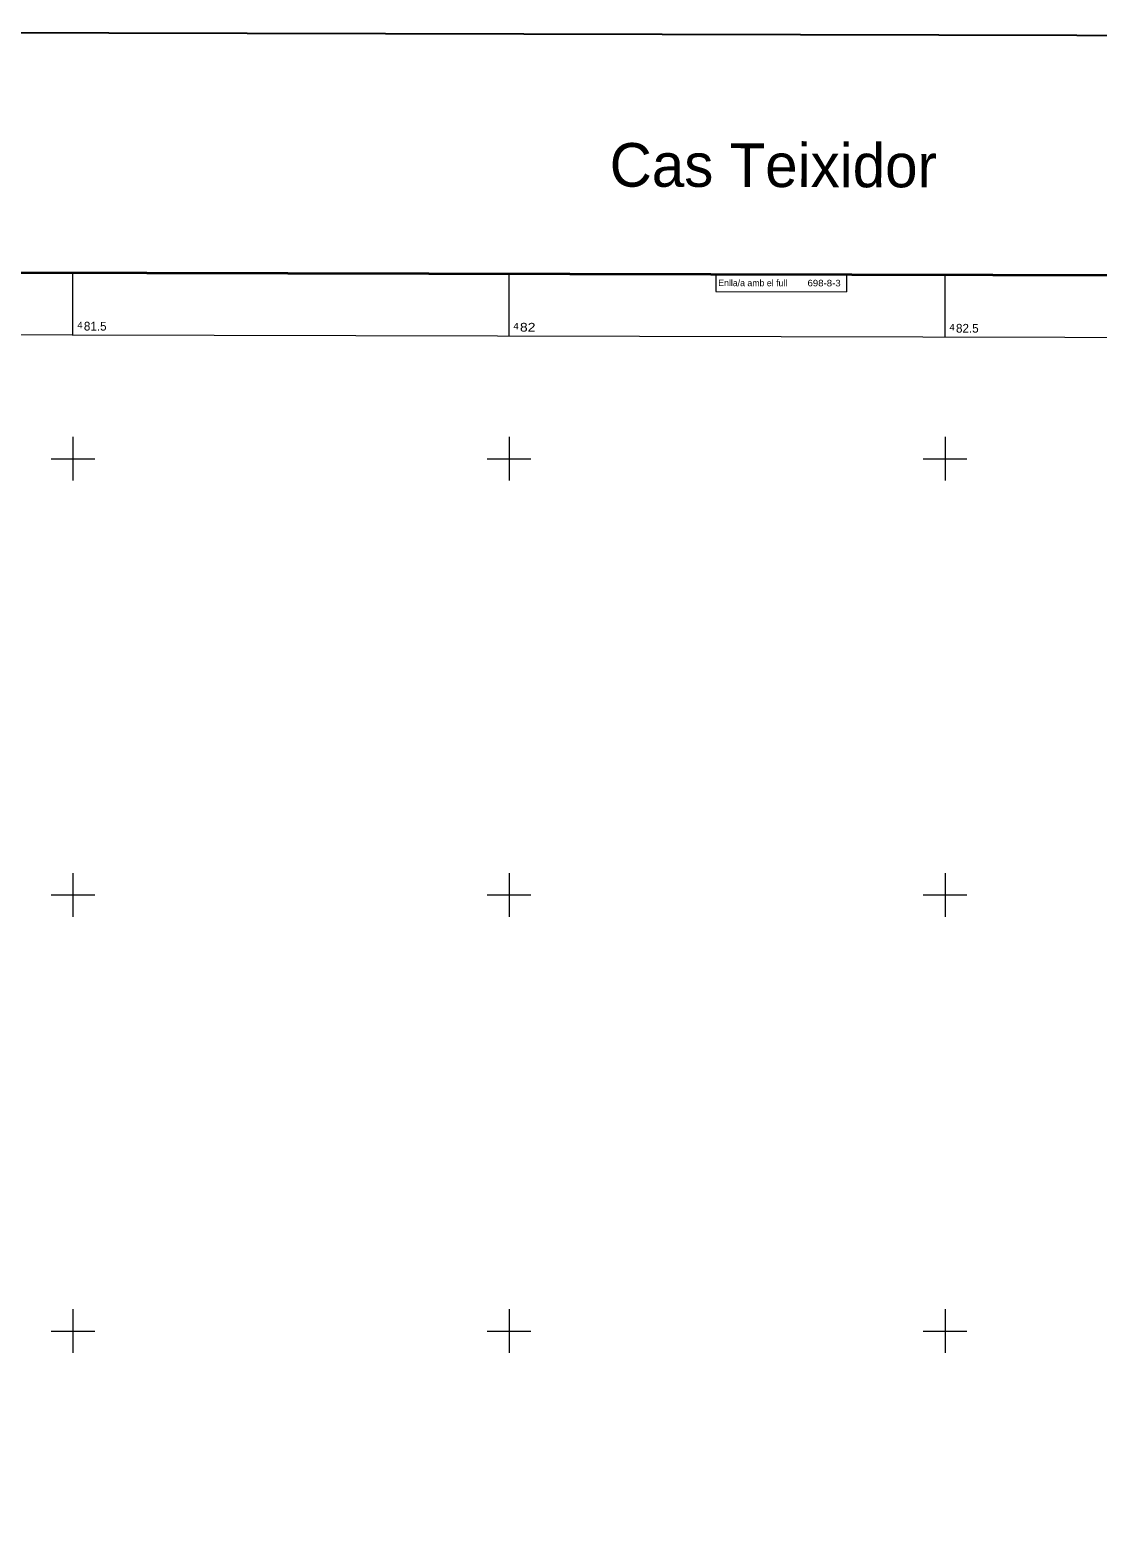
# Model space of a CAD drawing. Extents: x 480264 to 484872, y 4381275 to 4384491.
# Drawn here: x 481451 to 482675, y 4382763 to 4384491 of the extents above; entities that cross this region are included whole.
import ezdxf
from ezdxf.enums import TextEntityAlignment as Align

# ---------------------------------------------------------------- set-up
doc = ezdxf.new("R2010")
doc.units = 0
doc.header["$LTSCALE"] = 4
doc.linetypes.add('DOTTED', pattern=[1.5, 0.3, -1.2])
doc.layers.add('1', color=7, linetype='Continuous', lineweight=13)
doc.layers.add('2', color=7, linetype='DOTTED', lineweight=13)

msp = doc.modelspace()

# ---------------------------------------------------------------- linework, layer by layer
at = {"layer": '1'}
for p, q in [((481500, 4384142.05), (481500, 4384213.42)), ((482000, 4384140.85), (482000, 4384212.24)), ((482387.01, 4384211.32), (482386.97, 4384191.32)), ((482500, 4384139.65), (482500, 4384211.05)), ((481500, 4384025), (481500, 4383975)), ((482000, 4384025), (482000, 4383975)), ((482500, 4384025), (482500, 4383975)), ((481475, 4384000), (481525, 4384000)), ((481975, 4384000), (482025, 4384000)), ((482475, 4384000), (482525, 4384000)), ((481500, 4383525), (481500, 4383475)), ((482000, 4383525), (482000, 4383475)), ((482500, 4383525), (482500, 4383475)), ((481475, 4383500), (481525, 4383500)), ((481975, 4383500), (482025, 4383500)), ((482475, 4383500), (482525, 4383500)), ((481500, 4383025), (481500, 4382975)), ((482000, 4383025), (482000, 4382975)), ((482500, 4383025), (482500, 4382975)), ((481475, 4383000), (481525, 4383000)), ((481975, 4383000), (482025, 4383000)), ((482475, 4383000), (482525, 4383000))]:
    msp.add_line(p, q, dxfattribs=at)
at = {"layer": '1', "lineweight": 25}
msp.add_lwpolyline([(480271.92, 4384491.35), (484871.91, 4384480.42), (484864.3, 4381275.43), (480264.31, 4381286.36)], close=True, dxfattribs=at)
at = {"layer": '1', "lineweight": 35}
msp.add_lwpolyline([(480452.76, 4384215.91), (484171.26, 4384207.08), (484165.43, 4381752.09), (480446.93, 4381760.92)], close=True, dxfattribs=at)
at = {"layer": '1'}
msp.add_lwpolyline([(482237.01, 4384211.68), (482236.97, 4384191.68), (482386.97, 4384191.32)], dxfattribs=at)
msp.add_lwpolyline([(480523.1, 4384144.4), (484100.5, 4384135.8), (484095.6, 4381823.6), (480517.1, 4381832.1)], close=True, dxfattribs=at)

# ---------------------------------------------------------------- texts
at = {"layer": '2'}
msp.add_text('Cas Teixidor ', height=50, rotation=359.862, dxfattribs=at).set_placement((482312.29, 4384311.488), align=Align.CENTER)
for s, height, rotation, p in [('Enlla/a amb el full', 7.5, 359.864, (482239.86, 4384197.92)), ('81.5', 10, 359.862, (481512.48, 4384147.02)), ('82.5', 10, 359.862, (482512.48, 4384144.62))]:
    msp.add_text(s, height=height, rotation=rotation, dxfattribs=at).set_placement(p)
for s, height, rotation, width, p in [('698-8-3', 7.5, 359.864, 1.1, (482342.23, 4384197.68)), ('4', 7.5, 359.862, 1.1, (481504.98, 4384149.54)), ('4', 7.5, 359.862, 1.1, (482004.98, 4384148.34)), ('82  ', 10, 359.862, 1.2, (482012.48, 4384145.82)), ('4', 7.5, 359.862, 1.1, (482504.98, 4384147.14))]:
    msp.add_text(s, height=height, rotation=rotation, dxfattribs=dict(at, width=width)).set_placement(p)

doc.saveas('drawing.dxf')
